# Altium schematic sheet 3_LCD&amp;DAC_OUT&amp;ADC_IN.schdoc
size 309 x 223 mm; Symbol: Sheet-Symbol_A4; Device: Sheet-Symbol_A4; @Page Name: LCD&amp;DAC_OUT&amp;ADC_IN; @Create Date: 2023-05-13; @Page Count: 3; @Page No: 3; @Project Name: STM32_Wave&DSO; @Schematic Name: STM32_Wave&amp;DSO; @Update Date: 2023-05-14; Company: DGUT; Drawed: veis; Page Size: A4; Version: V1.0
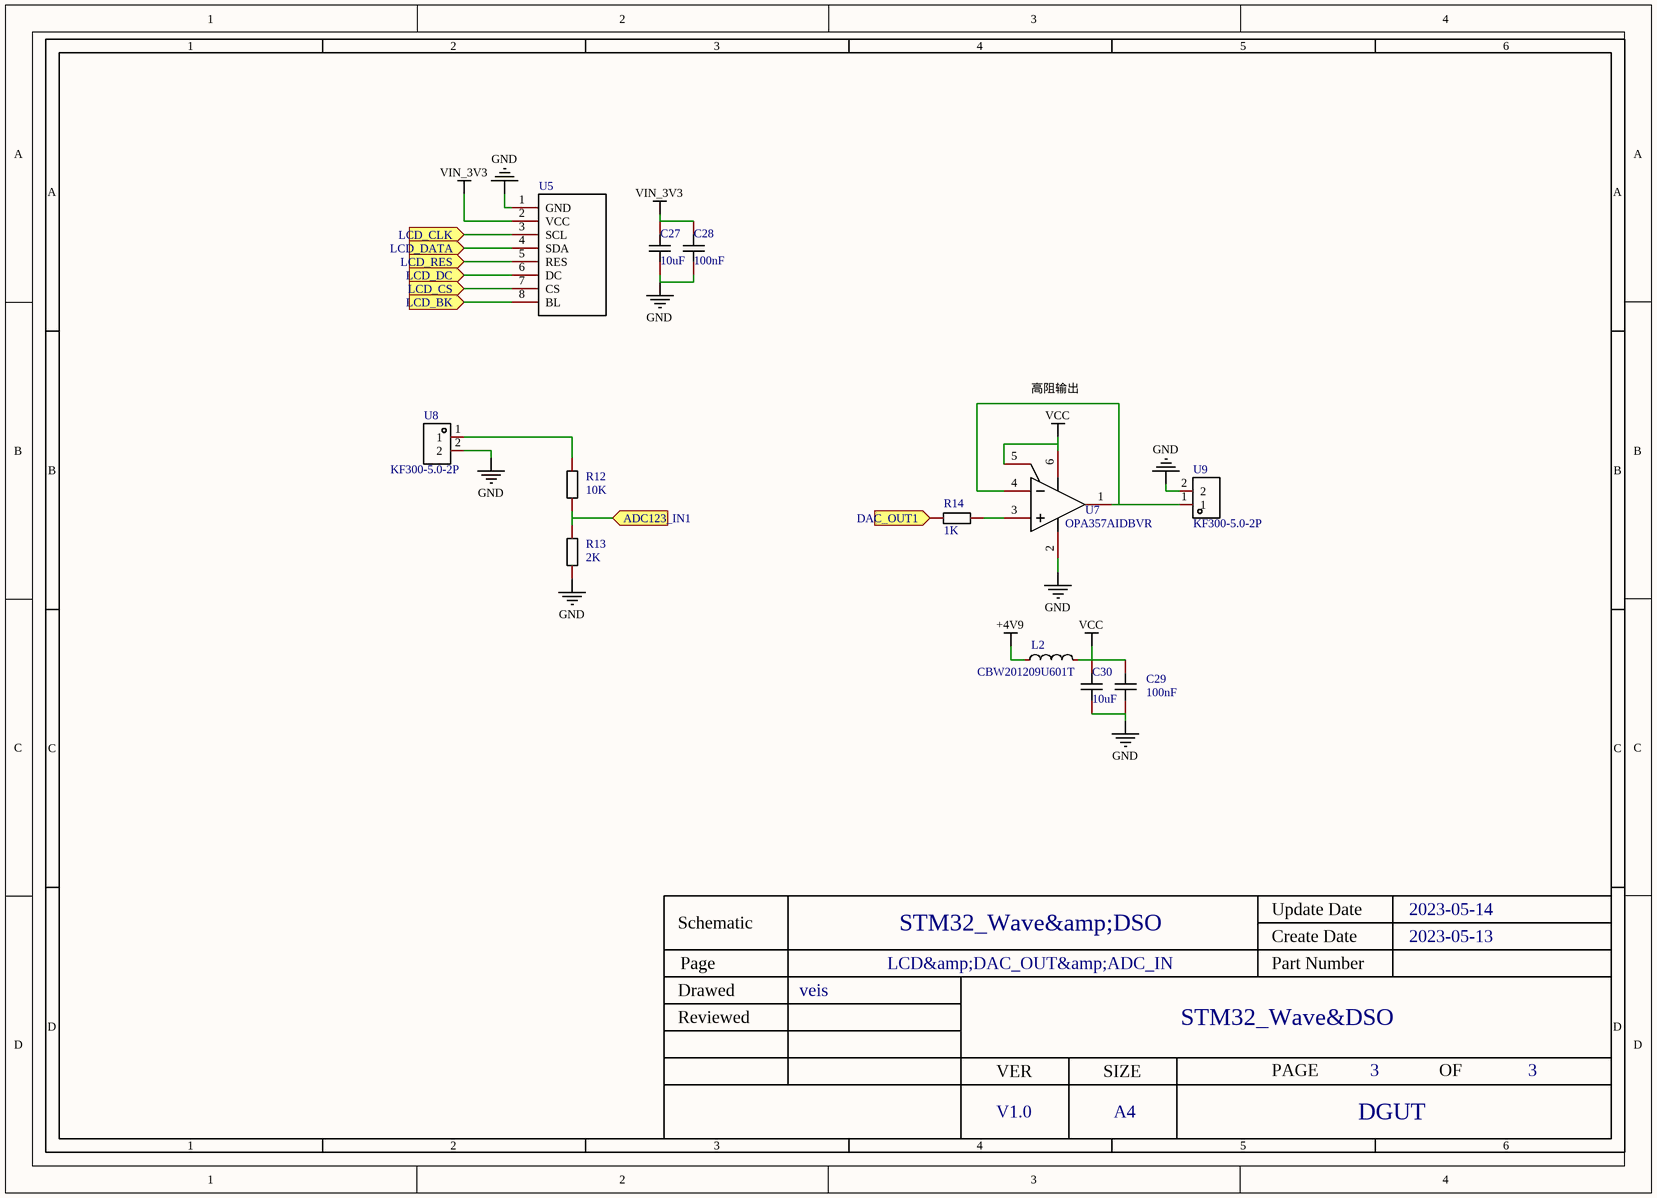
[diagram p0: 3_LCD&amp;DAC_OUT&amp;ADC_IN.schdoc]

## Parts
C27  10uF  [C0805]
C28  100nF  [C0603]
C29  100nF  [C0603]
C30  10uF  [C0805]
L2  CBW201209U601T  [L0805]
R12  10K  [R0603]
R13  2K  [R0603]
R14  1K  [R0603]
U5  TFT LCD 1.8  [TFT-LCD 1.8]  (value not drawn)
U7  OPA357AIDBVR  [SOT-23-6_L2.9-W1.6-P0.95-LS2.8-BR]
U8  KF300-5.0-2P  [CONN-TH_P5.00_KF300-5.0-2P]
U9  KF300-5.0-2P  [CONN-TH_P5.00_KF300-5.0-2P]

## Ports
ADC123_IN1 (in), DAC_OUT1 (in), LCD_BK (in), LCD_CLK (in), LCD_CS (in), LCD_DATA (in), LCD_DC (in), LCD_RES (in)

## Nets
+4V9: L2.1
GND: C27.1 C28.1 C29.1 C30.1 R13.2 U5.1(GND) U7.2(V-) U8.2 U9.2
VCC: C29.2 C30.2 L2.2 U7.5(ENABLE) U7.6(V+)
VIN_3V3: C27.2 C28.2 U5.2(VCC)
ADC123_IN1: R12.2 R13.1 ; port ADC123_IN1
DAC_OUT1: R14.1 ; port DAC_OUT1
LCD_BK: U5.8(BL) ; port LCD_BK
LCD_CLK: U5.3(SCL) ; port LCD_CLK
LCD_CS: U5.7(CS) ; port LCD_CS
LCD_DATA: U5.4(SDA) ; port LCD_DATA
LCD_DC: U5.6(DC) ; port LCD_DC
LCD_RES: U5.5(RES) ; port LCD_RES
NetR12_1: R12.1 U8.1
NetR14_2: R14.2 U7.3(IN+)
NetU7_1: U7.1(OUT) U7.4(IN-) U9.1

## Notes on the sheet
- 高阻输出

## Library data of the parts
C27 C30 = GRM21BR61H106KE43L: 容值:10uF;精度:±10%;额定电压:50V;材质(温度系数):X5R;; Manufacturer: muRata(村田); Add into BOM: yes; Tolerance: ±10%; Voltage Rated: 50V; Temperature Coefficient: X5R
C28 C29 = CC0603KRX7R9BB104: 容值:100nF;精度:±10%;额定电压:50V;材质(温度系数):X7R;; Manufacturer: YAGEO(国巨); Add into BOM: yes; Tolerance: ±10%; Voltage Rated: 50V; Temperature Coefficient: X7R
L2 = 磁珠 0805 600Ω@100MHz CBW201209U601T: Add into BOM: yes
R12-R14 = Res_0603: Symbol: 电阻; Convert to PCB: yes
U5 = TFT LCD 1.8: TFT LCD 1.8英寸，SPI接口; Add into BOM: yes
U7 = OPA357AIDBVR: 放大器组数:1;带宽(-3db):250MHz;输入偏置电流(Ib):3pA;输入失调电压(Vos):2mV;增益带宽积(GBP):100MHz;压摆率(SR):150V/us;; Manufacturer: TI(德州仪器); Add into BOM: yes; Number of Circuits: 1; -3db Bandwidth: 250MHz; Current - Input Bias(Ib): 3pA; Voltage - Input Offset(Vos): 2mV; Gain Bandwidth Product(GBP): 100MHz; Supply Current: 4.9mA
U8 U9 = KF300-5.0-2P: 间距:5mm;结构:1x2P;排数:1;每排PIN数:2;安装方式:直针;额定电流:17A;额定电压:250V;线规 - AWG:14~22;线规 - mm2:1.5;工作温度范围:-30℃~+120℃;颜色:蓝色;; Manufacturer: KEFA(科发); Add into BOM: yes; Pitch: 5mm; Structure: 1x2P; Number of PINs Per Row: 2; Current Rating (Max): 17A; Voltage Rating (Max): 250V; Wire Gauge - AWG: 14~22; Wire Gauge - mm2: 1.5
